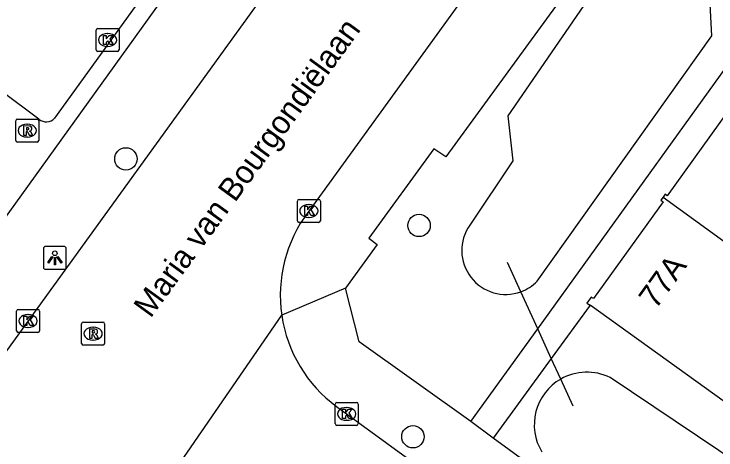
# Model space of a CAD drawing. Extents: x 159675 to 160530, y 382179 to 382901.
# Drawn here: x 160004.31 to 160034.9, y 382459.06 to 382478.05 of the extents above; entities that cross this region are included whole.
import ezdxf

# ---------------------------------------------------------------- set-up
doc = ezdxf.new("R2010")
doc.units = 0
for name, color, linetype in [('IMGEO_Boom', 7, 'Continuous'), ('IMGEO_Duiker', 7, 'Continuous'), ('IMGEO_Kolk', 7, 'Continuous'), ('IMGEO_Lichtpunt', 7, 'Continuous'), ('IMGEO_Openbare_ruimte_label', 7, 'Continuous'), ('IMGEO_Pand', 7, 'Continuous'), ('IMGEO_Pand_nummerreeks', 7, 'Continuous'), ('IMGEO_Parkeervlak_open', 7, 'Continuous'), ('IMGEO_Rijbaan_lokaal_open', 7, 'Continuous'), ('IMGEO_Rioolput', 7, 'Continuous'), ('IMGEO_Voetpad_open', 7, 'Continuous'), ('IMGEO_Waterloop', 7, 'Continuous')]:
    doc.layers.add(name, color=color, linetype=linetype)

msp = doc.modelspace()

# ---------------------------------------------------------------- linework, layer by layer
at = {"layer": 'IMGEO_Boom'}
for centre in [(160009.184, 382471.733), (160021.959, 382468.838), (160021.694, 382459.633)]:
    msp.add_circle(centre, 0.489, dxfattribs=at)
at = {"layer": 'IMGEO_Duiker'}
msp.add_lwpolyline([(160028.671, 382460.968), (160028.136, 382462.142), (160027.725, 382463.041), (160027.135, 382464.334), (160026.399, 382465.948), (160025.818, 382467.221)], dxfattribs=at)
at = {"layer": 'IMGEO_Kolk'}
for p, q in [((160007.885, 382476.49), (160007.885, 382477.342)), ((160007.96, 382477.416), (160008.812, 382477.416)), ((160008.373, 382477.196), (160008.398, 382477.196)), ((160008.886, 382477.342), (160008.886, 382476.49)), ((160008.396, 382476.636), (160008.371, 382476.636)), ((160008.812, 382476.416), (160007.96, 382476.416)), ((160016.657, 382469.043), (160016.657, 382469.895)), ((160016.732, 382469.969), (160017.584, 382469.969)), ((160017.658, 382469.895), (160017.658, 382469.043)), ((160017.145, 382469.749), (160017.17, 382469.749)), ((160017.584, 382468.969), (160016.732, 382468.969)), ((160017.168, 382469.189), (160017.143, 382469.189)), ((160004.418, 382464.251), (160004.418, 382465.103)), ((160004.493, 382465.177), (160005.345, 382465.177)), ((160004.906, 382464.957), (160004.931, 382464.957)), ((160005.419, 382465.103), (160005.419, 382464.251)), ((160004.929, 382464.397), (160004.904, 382464.397)), ((160005.345, 382464.177), (160004.493, 382464.177)), ((160018.306, 382460.201), (160018.306, 382461.053)), ((160018.381, 382461.127), (160019.233, 382461.127)), ((160019.307, 382461.053), (160019.307, 382460.201)), ((160018.794, 382460.907), (160018.819, 382460.907)), ((160018.817, 382460.347), (160018.792, 382460.347)), ((160019.233, 382460.127), (160018.381, 382460.127))]:
    msp.add_line(p, q, dxfattribs=at)
for points in [[(160007.885, 382476.49), (160007.885, 382477.342)], [(160007.96, 382477.416), (160008.812, 382477.416)], [(160008.886, 382477.342), (160008.886, 382476.49)], [(160008.206, 382477.116), (160008.329, 382477.116), (160008.329, 382476.965), (160008.459, 382477.116), (160008.623, 382477.116), (160008.477, 382476.965), (160008.63, 382476.716), (160008.478, 382476.716), (160008.393, 382476.88), (160008.329, 382476.813), (160008.329, 382476.716), (160008.206, 382476.716), (160008.206, 382477.116)], [(160008.812, 382476.416), (160007.96, 382476.416)], [(160016.657, 382469.043), (160016.657, 382469.895)], [(160016.732, 382469.969), (160017.584, 382469.969)], [(160017.658, 382469.895), (160017.658, 382469.043)], [(160016.978, 382469.669), (160017.101, 382469.669), (160017.101, 382469.518), (160017.231, 382469.669), (160017.395, 382469.669), (160017.249, 382469.518), (160017.402, 382469.269), (160017.25, 382469.269), (160017.165, 382469.433), (160017.101, 382469.366), (160017.101, 382469.269), (160016.978, 382469.269), (160016.978, 382469.669)], [(160017.584, 382468.969), (160016.732, 382468.969)], [(160004.418, 382464.251), (160004.418, 382465.103)], [(160004.493, 382465.177), (160005.345, 382465.177)], [(160005.419, 382465.103), (160005.419, 382464.251)], [(160004.739, 382464.877), (160004.862, 382464.877), (160004.862, 382464.726), (160004.992, 382464.877), (160005.156, 382464.877), (160005.01, 382464.726), (160005.163, 382464.477), (160005.011, 382464.477), (160004.926, 382464.641), (160004.862, 382464.574), (160004.862, 382464.477), (160004.739, 382464.477), (160004.739, 382464.877)], [(160005.345, 382464.177), (160004.493, 382464.177)], [(160018.306, 382460.201), (160018.306, 382461.053)], [(160018.381, 382461.127), (160019.233, 382461.127)], [(160019.307, 382461.053), (160019.307, 382460.201)], [(160018.627, 382460.827), (160018.75, 382460.827), (160018.75, 382460.676), (160018.88, 382460.827), (160019.044, 382460.827), (160018.898, 382460.676), (160019.051, 382460.427), (160018.899, 382460.427), (160018.814, 382460.591), (160018.75, 382460.524), (160018.75, 382460.427), (160018.627, 382460.427), (160018.627, 382460.827)], [(160019.233, 382460.127), (160018.381, 382460.127)]]:
    msp.add_lwpolyline(points, dxfattribs=at)
for centre, start, end in [((160007.962, 382477.34), 91.552, 178.448), ((160007.962, 382477.34), 91.552, 178.448), ((160008.81, 382477.34), 1.552, 88.448), ((160008.81, 382477.34), 1.552, 88.448), ((160007.962, 382476.492), 181.552, 268.448), ((160007.962, 382476.492), 181.552, 268.448), ((160008.81, 382476.492), 271.552, 358.448), ((160008.81, 382476.492), 271.552, 358.448), ((160016.734, 382469.893), 91.552, 178.448), ((160016.734, 382469.893), 91.552, 178.448), ((160017.582, 382469.893), 1.552, 88.448), ((160017.582, 382469.893), 1.552, 88.448), ((160016.734, 382469.045), 181.552, 268.448), ((160016.734, 382469.045), 181.552, 268.448), ((160017.582, 382469.045), 271.552, 358.448), ((160017.582, 382469.045), 271.552, 358.448), ((160004.495, 382465.101), 91.552, 178.448), ((160004.495, 382465.101), 91.552, 178.448), ((160005.343, 382465.101), 1.552, 88.448), ((160005.343, 382465.101), 1.552, 88.448), ((160004.495, 382464.253), 181.552, 268.448), ((160004.495, 382464.253), 181.552, 268.448), ((160005.343, 382464.253), 271.552, 358.448), ((160005.343, 382464.253), 271.552, 358.448), ((160018.383, 382461.051), 91.552, 178.448), ((160018.383, 382461.051), 91.552, 178.448), ((160019.231, 382461.051), 1.552, 88.448), ((160019.231, 382461.051), 1.552, 88.448), ((160018.383, 382460.203), 181.552, 268.448), ((160018.383, 382460.203), 181.552, 268.448), ((160019.231, 382460.203), 271.552, 358.448), ((160019.231, 382460.203), 271.552, 358.448)]:
    msp.add_arc(centre, 0.0765, start, end, dxfattribs=at)
for centre, major_axis, ratio, start_param, end_param in [((160008.372, 382476.916), (-0.387, 0.002), 0.722429, 4.712389, 7.853982), ((160008.397, 382476.916), (-0.39, 0.002), 0.717154, 1.570796, 4.712389), ((160017.144, 382469.469), (-0.387, 0.002), 0.722429, 4.712389, 7.853982), ((160017.169, 382469.469), (-0.39, 0.002), 0.717154, 1.570796, 4.712389), ((160004.905, 382464.677), (-0.387, 0.002), 0.722429, 4.712389, 7.853982), ((160004.93, 382464.677), (-0.39, 0.002), 0.717154, 1.570796, 4.712389), ((160018.793, 382460.627), (-0.387, 0.002), 0.722429, 4.712389, 7.853982), ((160018.818, 382460.627), (-0.39, 0.002), 0.717154, 1.570796, 4.712389)]:
    msp.add_ellipse(centre, major_axis=major_axis, ratio=ratio, start_param=start_param, end_param=end_param, dxfattribs=at)
at = {"layer": 'IMGEO_Lichtpunt'}
for p, q in [((160005.588, 382467.826), (160005.588, 382467.019)), ((160005.588, 382467.826), (160005.588, 382467.019)), ((160006.49, 382467.921), (160005.682, 382467.921)), ((160006.49, 382467.921), (160005.682, 382467.921)), ((160006.584, 382467.019), (160006.584, 382467.826)), ((160006.584, 382467.019), (160006.584, 382467.826)), ((160005.682, 382466.925), (160006.49, 382466.925)), ((160005.682, 382466.925), (160006.49, 382466.925))]:
    msp.add_line(p, q, dxfattribs=at)
for points in [[(160005.962, 382467.49), (160006.001, 382467.462), (160005.813, 382467.2), (160005.775, 382467.227), (160005.962, 382467.49)], [(160006.064, 382467.442), (160006.111, 382467.442), (160006.111, 382467.12), (160006.064, 382467.12), (160006.064, 382467.442)], [(160006.174, 382467.462), (160006.212, 382467.489), (160006.399, 382467.227), (160006.36, 382467.199), (160006.174, 382467.462)]]:
    msp.add_lwpolyline(points, dxfattribs=at)
msp.add_circle((160006.087, 382467.624), 0.0994, dxfattribs=at)
for centre, start, end in [((160005.682, 382467.826), 90, 180), ((160005.682, 382467.826), 90, 180), ((160006.49, 382467.826), 0, 90), ((160006.49, 382467.826), 0, 90), ((160005.682, 382467.019), 180, 270), ((160005.682, 382467.019), 180, 270), ((160006.49, 382467.019), 270, 0), ((160006.49, 382467.019), 270, 360)]:
    msp.add_arc(centre, 0.0946, start, end, dxfattribs=at)
at = {"layer": 'IMGEO_Pand'}
for points in [[(160037.64, 382473.43), (160035.91, 382474.671), (160035.721, 382474.409), (160035.811, 382474.345), (160032.781, 382470.131), (160032.692, 382470.195), (160032.597, 382470.065)], [(160032.597, 382470.065), (160032.503, 382469.934), (160032.593, 382469.87), (160029.557, 382465.648), (160029.467, 382465.712), (160029.28, 382465.451), (160029.413, 382465.356)], [(160032.597, 382470.065), (160040.276, 382464.504)], [(160036.972, 382459.928), (160029.413, 382465.356)]]:
    msp.add_lwpolyline(points, dxfattribs=at)
at = {"layer": 'IMGEO_Parkeervlak_open'}
for points in [[(160016.763, 382488.325), (160006.076, 382473.508)], [(160005.388, 382473.465), (160002.211, 382475.832)]]:
    msp.add_lwpolyline(points, dxfattribs=at)
msp.add_arc((160005.709, 382473.859), 0.508, 230.831, 316.3216, dxfattribs=at)
at = {"layer": 'IMGEO_Rijbaan_lokaal_open'}
for points in [[(160051.574, 382516.842), (160051.402, 382516.632), (160041.091, 382502.494), (160017.12, 382469.419)], [(159989.893, 382443.905), (160000, 382457.874), (160020.333, 382485.978)], [(160010.202, 382456.532), (160015.978, 382464.923)], [(160018.366, 382460.946), (160123.455, 382384.426)]]:
    msp.add_lwpolyline(points, dxfattribs=at)
for centre, radius, start, end in [((160021.94, 382465.802), 6.026, 143.1121, 188.384), ((160021.943, 382465.799), 6.029, 188.3581, 233.6076)]:
    msp.add_arc(centre, radius, start, end, dxfattribs=at)
at = {"layer": 'IMGEO_Rioolput'}
for p, q in [((160004.383, 382472.543), (160004.383, 382473.395)), ((160004.458, 382473.469), (160005.31, 382473.469)), ((160004.871, 382473.249), (160004.896, 382473.249)), ((160005.384, 382473.395), (160005.384, 382472.543)), ((160004.894, 382472.689), (160004.869, 382472.689)), ((160005.31, 382472.469), (160004.458, 382472.469)), ((160007.328, 382464.623), (160008.18, 382464.623)), ((160007.253, 382463.697), (160007.253, 382464.549)), ((160007.741, 382464.403), (160007.766, 382464.403)), ((160008.254, 382464.549), (160008.254, 382463.697)), ((160007.764, 382463.843), (160007.739, 382463.843)), ((160008.18, 382463.623), (160007.328, 382463.623))]:
    msp.add_line(p, q, dxfattribs=at)
for points in [[(160004.383, 382472.543), (160004.383, 382473.395)], [(160004.458, 382473.469), (160005.31, 382473.469)], [(160004.972, 382473.167), (160004.72, 382473.169), (160004.72, 382472.769)], [(160005.384, 382473.395), (160005.384, 382472.543)], [(160004.72, 382472.769), (160004.844, 382472.769), (160004.844, 382472.931), (160004.855, 382472.931)], [(160004.898, 382473.088), (160004.844, 382473.088), (160004.844, 382473.007)], [(160004.844, 382473.007), (160004.896, 382473.007)], [(160004.902, 382472.902), (160004.973, 382472.769), (160005.113, 382472.769), (160005.048, 382472.895)], [(160005.31, 382472.469), (160004.458, 382472.469)], [(160007.328, 382464.623), (160008.18, 382464.623)], [(160007.253, 382463.697), (160007.253, 382464.549)], [(160007.842, 382464.321), (160007.59, 382464.323), (160007.59, 382463.923)], [(160008.254, 382464.549), (160008.254, 382463.697)], [(160007.59, 382463.923), (160007.714, 382463.923), (160007.714, 382464.085), (160007.725, 382464.085)], [(160007.768, 382464.242), (160007.714, 382464.242), (160007.714, 382464.161)], [(160007.714, 382464.161), (160007.766, 382464.161)], [(160007.772, 382464.056), (160007.843, 382463.923), (160007.983, 382463.923), (160007.918, 382464.049)], [(160008.18, 382463.623), (160007.328, 382463.623)]]:
    msp.add_lwpolyline(points, dxfattribs=at)
for centre, radius, start, end in [((160004.46, 382473.393), 0.0765, 91.552, 178.448), ((160004.46, 382473.393), 0.0765, 91.552, 178.448), ((160005.308, 382473.393), 0.0765, 1.552, 88.448), ((160005.308, 382473.393), 0.0765, 1.552, 88.448), ((160004.854, 382472.878), 0.0533, 26.0293, 88.6989), ((160004.88, 382473.196), 0.19, 274.7715, 282.9687), ((160004.904, 382472.992), 0.0964, 77.0061, 93.1865), ((160004.918, 382473.049), 0.0378, 276.6634, 79.6772), ((160004.971, 382473.057), 0.109, 350.3612, 89.416), ((160004.969, 382473.057), 0.112, 277.5842, 350.9817), ((160004.953, 382472.842), 0.108, 29.5134, 73.7905), ((160004.46, 382472.545), 0.0765, 181.552, 268.448), ((160004.46, 382472.545), 0.0765, 181.552, 268.448), ((160005.308, 382472.545), 0.0765, 271.552, 358.448), ((160005.308, 382472.545), 0.0765, 271.552, 358.448), ((160007.33, 382464.547), 0.0765, 91.552, 178.448), ((160007.33, 382464.547), 0.0765, 91.552, 178.448), ((160008.178, 382464.547), 0.0765, 1.552, 88.448), ((160008.178, 382464.547), 0.0765, 1.552, 88.448), ((160007.841, 382464.211), 0.109, 350.3612, 89.416), ((160007.724, 382464.032), 0.0533, 26.0293, 88.6989), ((160007.75, 382464.35), 0.19, 274.7715, 282.9687), ((160007.774, 382464.146), 0.0964, 77.0061, 93.1865), ((160007.788, 382464.203), 0.0378, 276.6634, 79.6772), ((160007.839, 382464.211), 0.112, 277.5842, 350.9817), ((160007.823, 382463.996), 0.108, 29.5134, 73.7905), ((160007.33, 382463.699), 0.0765, 181.552, 268.448), ((160007.33, 382463.699), 0.0765, 181.552, 268.448), ((160008.178, 382463.699), 0.0765, 271.552, 358.448), ((160008.178, 382463.699), 0.0765, 271.552, 358.448)]:
    msp.add_arc(centre, radius, start, end, dxfattribs=at)
for centre, major_axis, ratio, start_param, end_param in [((160004.87, 382472.969), (-0.387, 0.002), 0.722429, 4.712389, 7.853982), ((160004.895, 382472.969), (-0.39, 0.002), 0.717154, 1.570796, 4.712389), ((160007.74, 382464.123), (-0.387, 0.002), 0.722429, 4.712389, 7.853982), ((160007.765, 382464.123), (-0.39, 0.002), 0.717154, 1.570796, 4.712389)]:
    msp.add_ellipse(centre, major_axis=major_axis, ratio=ratio, start_param=start_param, end_param=end_param, dxfattribs=at)
at = {"layer": 'IMGEO_Voetpad_open'}
for points in [[(160017.37, 382487.892), (160000, 382463.753), (159985.646, 382443.958)], [(160024.222, 382460.289), (160027.135, 382464.334), (160037.642, 382478.923), (160031.503, 382483.33), (160023.13, 382471.823), (160022.611, 382472.173), (160019.765, 382468.28), (160020.141, 382468.006), (160019.056, 382466.519), (160018.758, 382466.11)], [(160018.758, 382466.11), (160015.978, 382464.923)], [(160024.222, 382460.289), (160019.353, 382463.773), (160018.758, 382466.11)], [(160029.413, 382465.356), (160027.725, 382463.041), (160025.191, 382459.567)], [(160025.191, 382459.567), (160024.222, 382460.289)], [(160043.937, 382454.91), (160041.474, 382451.508), (160039.671, 382449.018), (160025.191, 382459.567)]]:
    msp.add_lwpolyline(points, dxfattribs=at)
at = {"layer": 'IMGEO_Waterloop'}
for points in [[(160027.109, 382466.407), (160034.727, 382477.095), (160034.57, 382479.891), (160033.065, 382481.347)], [(160030.567, 382480.511), (160025.83, 382473.609), (160026.045, 382471.654), (160024.17, 382468.849)], [(160040.732, 382455.196), (160030.284, 382462.211)]]:
    msp.add_lwpolyline(points, dxfattribs=at)
for centre, radius, start, end in [((160025.738, 382467.747), 1.916, 144.891, 290.1831), ((160025.741, 382467.744), 1.913, 290.1162, 315.6474), ((160029.275, 382460.154), 2.291, 63.8665, 119.8132), ((160029.276, 382460.152), 2.294, 119.8003, 211.102)]:
    msp.add_arc(centre, radius, start, end, dxfattribs=at)

# ---------------------------------------------------------------- texts
at = {"layer": 'IMGEO_Openbare_ruimte_label'}
msp.add_text('Maria van Bourgondiëlaan', height=1, rotation=53.9094, dxfattribs=at).set_placement((160010.258, 382464.761))
at = {"layer": 'IMGEO_Pand_nummerreeks'}
msp.add_text('77A', height=1, rotation=54.282, dxfattribs=at).set_placement((160032.278, 382465.149))

doc.saveas('drawing.dxf')
